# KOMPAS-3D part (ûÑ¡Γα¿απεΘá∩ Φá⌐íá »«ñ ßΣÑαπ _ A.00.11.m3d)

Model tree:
1. Эскиз:1
2. Операция выдавливания:1
     Расстояние 1 = 12
3. Эскиз:2
4. Вырезать элемент вращения:1
     Угол 1 = 360
5. Эскиз:3
6. Вырезать элемент выдавливания:1  (labels: A.00.11)
     Расстояние 1 = 10

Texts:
  Центрирующая шайба под сферу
